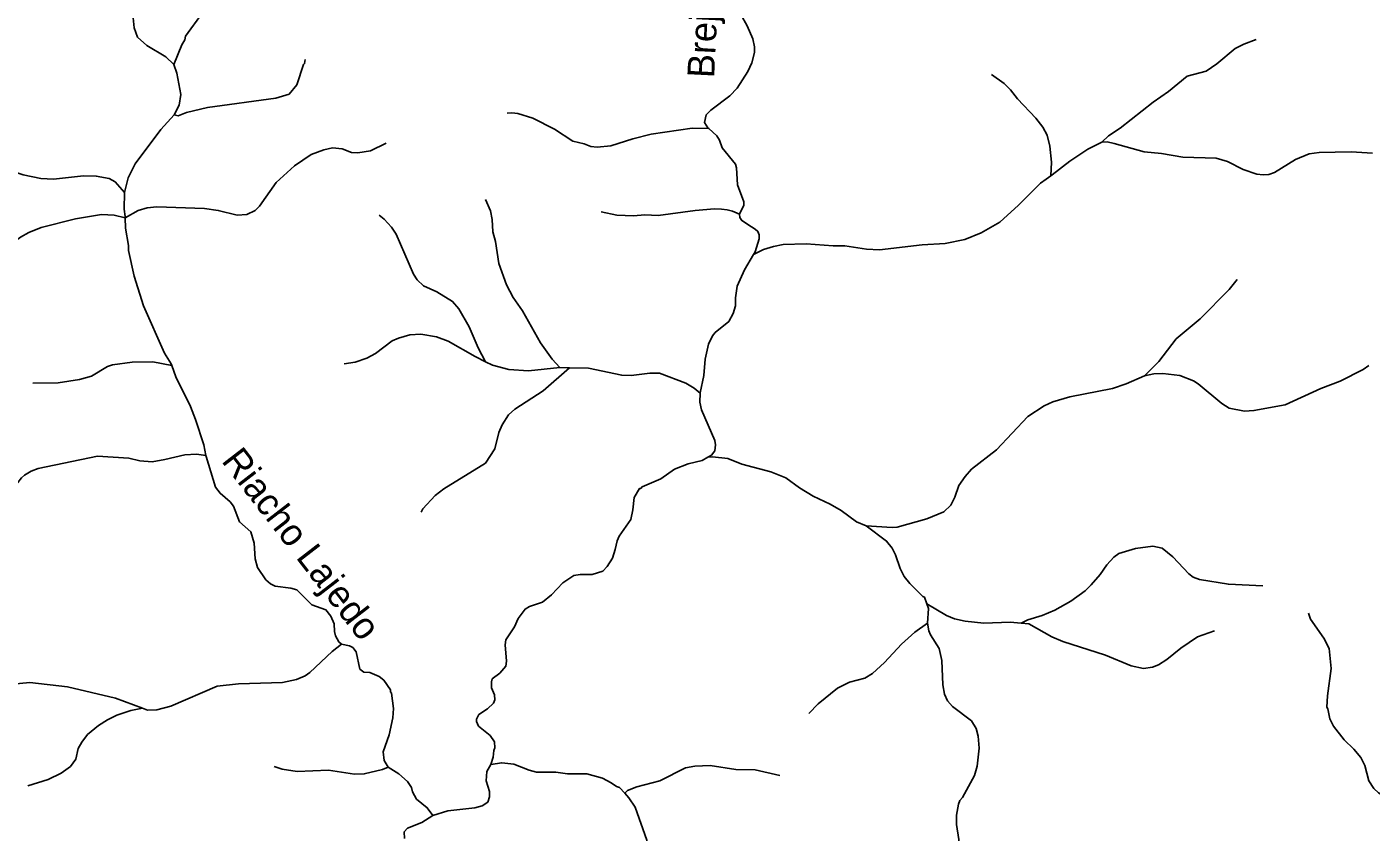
# Model space of a CAD drawing. Extents: x 280.4 to 335.6, y 8893.9 to 8949.5.
# Drawn here: x 294.07 to 304.07, y 8901.81 to 8907.81 of the extents above; entities that cross this region are included whole.
import ezdxf
from ezdxf.enums import TextEntityAlignment as Align

# ---------------------------------------------------------------- set-up
doc = ezdxf.new("R2010")
doc.units = 0
doc.header["$LTSCALE"] = 0.064
doc.layers.add('61', color=7, linetype='Continuous')
doc.layers.add('7', color=7, linetype='Continuous', lineweight=25)

msp = doc.modelspace()

# ---------------------------------------------------------------- linework, layer by layer
at = {"layer": '7'}
msp.add_line((298.0338, 8905.2741), (298.1057, 8905.2723), dxfattribs=at)
for points in [[(294.8695, 8909.4372), (294.8283, 8909.3018), (294.8149, 8909.1389), (294.8292, 8908.9278), (294.8261, 8908.7854), (294.8339, 8908.6824), (294.8294, 8908.6447), (294.8548, 8908.2587), (294.8485, 8907.9772), (294.8641, 8907.8037), (294.8903, 8907.7352), (294.9604, 8907.6727), (295.1005, 8907.5881), (295.1595, 8907.5317)], [(295.7286, 8908.5113), (295.6344, 8908.4215), (295.5944, 8908.3911), (295.545, 8908.3341), (295.5236, 8908.2978), (295.5089, 8908.2555), (295.4944, 8908.1353), (295.4452, 8908.056), (295.4328, 8908.0148), (295.3726, 8907.9159), (295.2472, 8907.742), (295.242, 8907.7151), (295.2196, 8907.6788), (295.1595, 8907.5317)], [(299.5995, 8908.4727), (299.5837, 8908.4131), (299.5528, 8908.3621), (299.4083, 8908.1337), (299.3696, 8907.9971), (299.3708, 8907.936), (299.3805, 8907.905), (299.429, 8907.8189), (299.47, 8907.7227), (299.4831, 8907.6637), (299.483, 8907.6204), (299.4626, 8907.5439), (299.4338, 8907.4796), (299.354, 8907.3549), (299.2995, 8907.2988), (299.1586, 8907.1913), (299.1244, 8907.1555), (299.1108, 8907.1), (299.1368, 8907.0604), (299.1432, 8907.0543)], [(303.2179, 8907.7171), (303.1251, 8907.6829), (303.061, 8907.6512), (302.9262, 8907.5368), (302.8453, 8907.4825), (302.7046, 8907.4438), (302.5663, 8907.3303), (302.4507, 8907.2508), (302.2057, 8907.0574), (302.1194, 8906.9994), (302.069, 8906.9533)], [(296.1383, 8907.5687), (296.1335, 8907.5381), (296.1259, 8907.5321), (296.0763, 8907.3792), (296.0182, 8907.3101), (295.9188, 8907.2795), (295.4107, 8907.2101), (295.2547, 8907.1735), (295.1931, 8907.1499), (295.1615, 8907.1572)], [(295.1595, 8907.5317), (295.1828, 8907.4657), (295.213, 8907.3069), (295.1998, 8907.228), (295.1615, 8907.1572)], [(301.2477, 8907.4576), (301.3414, 8907.3894), (301.3899, 8907.3425), (301.4401, 8907.2755), (301.5781, 8907.1319), (301.6293, 8907.0647), (301.6615, 8907.0048), (301.6817, 8906.922), (301.6933, 8906.804), (301.6899, 8906.7017)], [(295.1615, 8907.1572), (295.064, 8907.0479), (294.8719, 8906.7911), (294.8213, 8906.6857), (294.7927, 8906.5766)], [(297.643, 8907.1676), (297.6764, 8907.1717), (297.7201, 8907.1656), (297.8333, 8907.1317), (297.9946, 8907.0492), (298.1312, 8906.9596), (298.2162, 8906.9396), (298.2638, 8906.9194), (298.3118, 8906.9145), (298.4138, 8906.9245), (298.5786, 8906.9769), (298.7136, 8907.0122), (299.0193, 8907.0567), (299.1432, 8907.0543)], [(293.4645, 8907.075), (293.4843, 8907.0451), (293.503, 8907.022), (293.5465, 8906.9755), (293.7187, 8906.8413), (293.848, 8906.7734), (294.0376, 8906.7086), (294.17, 8906.6822), (294.2639, 8906.6762), (294.487, 8906.7017), (294.5829, 8906.7001), (294.6796, 8906.6821), (294.7243, 8906.656), (294.7927, 8906.5766)], [(299.1432, 8907.0543), (299.2016, 8906.999), (299.222, 8906.9678), (299.2427, 8906.9112), (299.3423, 8906.7888), (299.3487, 8906.7617), (299.3557, 8906.6348), (299.4031, 8906.5091), (299.4027, 8906.4839), (299.3705, 8906.4168)], [(296.741, 8906.9446), (296.6242, 8906.8892), (296.529, 8906.873), (296.4818, 8906.8758), (296.4144, 8906.9019), (296.3422, 8906.9111), (296.2775, 8906.8966), (296.1829, 8906.8604), (296.0576, 8906.7768), (295.9221, 8906.6523), (295.7984, 8906.4747), (295.7658, 8906.4439), (295.7035, 8906.4126), (295.6314, 8906.4092), (295.4913, 8906.4442), (295.3875, 8906.4585), (295.0339, 8906.4714), (294.9619, 8906.4631), (294.894, 8906.4444), (294.7989, 8906.3885)], [(302.069, 8906.9533), (301.9658, 8906.9004), (301.8302, 8906.81), (301.6984, 8906.7094), (301.6899, 8906.7017)], [(304.0851, 8906.8713), (303.9252, 8906.8806), (303.6866, 8906.876), (303.6131, 8906.8649), (303.5101, 8906.8232), (303.3549, 8906.7259), (303.3115, 8906.711), (303.2702, 8906.7082), (303.2227, 8906.7145), (303.1205, 8906.748), (303.0039, 8906.8075), (302.9199, 8906.8325), (302.6728, 8906.8408), (302.5138, 8906.8678), (302.3834, 8906.881), (302.1609, 8906.943), (302.1081, 8906.9542), (302.069, 8906.9533)], [(301.6899, 8906.7017), (301.654, 8906.678), (301.6119, 8906.6459), (301.4497, 8906.4821), (301.3104, 8906.356), (301.1716, 8906.2777), (301.0499, 8906.2276), (300.9025, 8906.1979), (300.7306, 8906.1867), (300.4145, 8906.1516), (300.3181, 8906.1557), (300.1564, 8906.1802), (300.0677, 8906.1805), (299.8669, 8906.1963), (299.6958, 8906.19), (299.6248, 8906.1747), (299.5509, 8906.1533), (299.4759, 8906.1159)], [(294.7927, 8906.5766), (294.7908, 8906.4524), (294.7987, 8906.4), (294.7989, 8906.3885)], [(297.48, 8906.5262), (297.5179, 8906.4413), (297.5306, 8906.3773), (297.5352, 8906.2833), (297.5539, 8906.212), (297.5804, 8906.0476), (297.6373, 8905.89), (297.6872, 8905.796), (297.7552, 8905.6958), (297.8898, 8905.4571), (297.9778, 8905.3349), (298.0338, 8905.2741)], [(298.3421, 8906.433), (298.4571, 8906.4091), (298.5826, 8906.4043), (298.6657, 8906.4121), (298.7662, 8906.4058), (299.0424, 8906.4443), (299.1864, 8906.457), (299.2387, 8906.4526), (299.2791, 8906.4488), (299.3196, 8906.4378), (299.3705, 8906.4168)], [(292.5427, 8905.3746), (292.64, 8905.3696), (292.7205, 8905.3528), (292.8704, 8905.306), (293.0055, 8905.2516), (293.0877, 8905.2352), (293.1335, 8905.2414), (293.1904, 8905.2819), (293.24, 8905.3409), (293.4092, 8905.6973), (293.4775, 8905.7946), (293.5368, 8905.8586), (293.735, 8906.0343), (294.0186, 8906.2449), (294.0802, 8906.2791), (294.1735, 8906.3179), (294.4287, 8906.3817), (294.6213, 8906.4138), (294.7156, 8906.4081), (294.7989, 8906.3885)], [(294.7989, 8906.3885), (294.8003, 8906.3112), (294.8225, 8906.1819), (294.8235, 8906.1455), (294.8649, 8905.9548), (294.9347, 8905.7333), (295.0896, 8905.3814), (295.1407, 8905.3007), (295.1452, 8905.2879)], [(296.6893, 8906.4094), (296.7255, 8906.3795), (296.7813, 8906.3183), (296.8157, 8906.2662), (296.9452, 8905.9692), (296.9707, 8905.9277), (297.0178, 8905.8811), (297.1194, 8905.8365), (297.2357, 8905.7665), (297.2815, 8905.7115), (297.3593, 8905.5758), (297.426, 8905.4204), (297.4803, 8905.3167)], [(299.3705, 8906.4168), (299.3742, 8906.3911), (299.3891, 8906.3684), (299.46, 8906.3228), (299.4893, 8906.3046), (299.5084, 8906.2871), (299.5178, 8906.2613), (299.5183, 8906.2316), (299.4877, 8906.1363), (299.4759, 8906.1159)], [(299.4759, 8906.1159), (299.4099, 8906.0018), (299.3552, 8905.8797), (299.3424, 8905.794), (299.342, 8905.7341), (299.325, 8905.6757), (299.2922, 8905.6169), (299.191, 8905.5347), (299.1713, 8905.5102), (299.1407, 8905.4472), (299.1158, 8905.3355), (299.1056, 8905.2145), (299.0795, 8905.0849), (299.0793, 8905.0817)], [(303.0767, 8905.93), (303.0163, 8905.8547), (302.802, 8905.6374), (302.6237, 8905.4874), (302.4924, 8905.3178), (302.3876, 8905.2117)], [(296.4294, 8905.3003), (296.5107, 8905.314), (296.5974, 8905.3421), (296.662, 8905.3776), (296.7868, 8905.4733), (296.8317, 8905.4925), (296.9173, 8905.5164), (296.9995, 8905.5213), (297.1155, 8905.5023), (297.2018, 8905.4689), (297.4048, 8905.3547), (297.4803, 8905.3167)], [(294.1111, 8905.1567), (294.2983, 8905.1585), (294.4576, 8905.1839), (294.5477, 8905.21), (294.6656, 8905.2819), (294.7046, 8905.2927), (294.8491, 8905.3135), (295.0027, 8905.3166), (295.1452, 8905.2879)], [(295.1452, 8905.2879), (295.1751, 8905.2035), (295.2834, 8904.9841), (295.3224, 8904.8865), (295.384, 8904.6969), (295.3989, 8904.6189)], [(297.0005, 8904.1954), (297.0152, 8904.221), (297.1064, 8904.3201), (297.1695, 8904.3704), (297.4803, 8904.5615), (297.5509, 8904.6668), (297.5804, 8904.7896), (297.6052, 8904.8459), (297.652, 8904.9201), (297.6989, 8904.9621), (297.9094, 8905.0993), (298.1057, 8905.2723)], [(297.4803, 8905.3167), (297.5332, 8905.29), (297.654, 8905.2597), (297.8015, 8905.248), (298.0338, 8905.2741)], [(298.1057, 8905.2723), (298.2478, 8905.2687), (298.4947, 8905.2161), (298.5651, 8905.2145), (298.7041, 8905.2303), (298.7755, 8905.2304), (298.972, 8905.158), (299.0353, 8905.12), (299.0793, 8905.0817)], [(304.0565, 8905.288), (304.0138, 8905.2584), (303.8433, 8905.1715), (303.6994, 8905.117), (303.4352, 8904.9957), (303.2008, 8904.9522), (303.1319, 8904.949), (303.0168, 8904.9701), (302.9622, 8905.0045), (302.787, 8905.1525), (302.7511, 8905.1756), (302.6489, 8905.2146), (302.5234, 8905.2288), (302.4569, 8905.227), (302.3876, 8905.2117)], [(302.3876, 8905.2117), (302.2512, 8905.1522), (302.149, 8905.1164), (301.8316, 8905.0546), (301.7045, 8905.0182), (301.6396, 8904.9893), (301.5179, 8904.9078), (301.2844, 8904.66), (301.0995, 8904.515), (301.0508, 8904.4613), (301.005, 8904.3939), (300.9739, 8904.3067), (300.9451, 8904.2491), (300.8926, 8904.1978), (300.7673, 8904.1472), (300.545, 8904.0838), (300.5084, 8904.0807), (300.3135, 8904.0941)], [(299.0793, 8905.0817), (299.0762, 8905.0161), (299.088, 8904.9593), (299.1869, 8904.7289), (299.1921, 8904.6966), (299.1873, 8904.6522), (299.1622, 8904.6209), (299.1354, 8904.6056)], [(293.7359, 8903.4204), (293.8149, 8903.5442), (293.8423, 8903.6017), (293.8763, 8903.699), (293.9003, 8903.8158), (293.9037, 8903.9683), (293.9137, 8904.0196), (293.9146, 8904.0245), (293.951, 8904.1397), (293.9435, 8904.2555), (293.9724, 8904.381), (294.0251, 8904.4518), (294.0477, 8904.4726), (294.0985, 8904.5011), (294.1512, 8904.5203), (294.5919, 8904.6129), (294.8253, 8904.5971), (294.9071, 8904.5784), (294.9988, 8904.5716), (295.0924, 8904.5871), (295.2425, 8904.6227), (295.3282, 8904.629), (295.3989, 8904.6189)], [(295.3989, 8904.6189), (295.4006, 8904.6098), (295.4694, 8904.3824), (295.5048, 8904.3373), (295.5797, 8904.272), (295.6039, 8904.2403), (295.6501, 8904.1234), (295.7345, 8904.0494), (295.7582, 8903.9644), (295.7661, 8903.8482), (295.7831, 8903.7836), (295.8444, 8903.6926), (295.8806, 8903.6612), (295.9137, 8903.6456), (296.0324, 8903.63), (296.0755, 8903.6171), (296.1883, 8903.5054), (296.2924, 8903.4678), (296.3289, 8903.4205), (296.353, 8903.3631), (296.3567, 8903.3057), (296.365, 8903.2754), (296.3896, 8903.2289), (296.4087, 8903.2135)], [(299.1354, 8904.6056), (299.0932, 8904.5815), (298.9905, 8904.5555), (298.8866, 8904.5162), (298.7851, 8904.4432), (298.6459, 8904.3846), (298.6359, 8904.3723), (298.6272, 8904.3723), (298.5886, 8904.3051), (298.5777, 8904.2125)], [(300.3135, 8904.0941), (300.2436, 8904.1246), (300.1296, 8904.2086), (300.0474, 8904.2553), (299.9202, 8904.3149), (299.8189, 8904.3771), (299.7168, 8904.4513), (299.6054, 8904.4968), (299.3879, 8904.5524), (299.2851, 8904.5965), (299.1714, 8904.6086), (299.1354, 8904.6056)], [(298.5777, 8904.2125), (298.5614, 8904.1423), (298.4748, 8904.0164), (298.4596, 8903.9829), (298.4466, 8903.9183), (298.4252, 8903.8535), (298.386, 8903.7911), (298.3542, 8903.7563), (298.2755, 8903.7303), (298.1845, 8903.7302), (298.1392, 8903.7234), (298.056, 8903.669), (297.9729, 8903.5794), (297.906, 8903.5245), (297.8072, 8903.4935), (297.7758, 8903.4732), (297.7244, 8903.4047), (297.697, 8903.3407), (297.6315, 8903.2441), (297.6265, 8903.2075), (297.6376, 8903.0858), (297.6309, 8903.0476), (297.5873, 8902.9972), (297.5308, 8902.9537), (297.5242, 8902.9306), (297.5257, 8902.8874), (297.5472, 8902.8344), (297.551, 8902.7981), (297.5412, 8902.7719), (297.4943, 8902.7312), (297.4304, 8902.6879), (297.4123, 8902.6525), (297.4131, 8902.6363), (297.4282, 8902.6014), (297.5159, 8902.5307), (297.5466, 8902.4859), (297.5496, 8902.4409), (297.5419, 8902.419), (297.5383, 8902.3709), (297.5193, 8902.3151)], [(300.7674, 8903.5127), (300.7487, 8903.563), (300.7366, 8903.5678), (300.6394, 8903.6646), (300.5963, 8903.7176), (300.5675, 8903.7751), (300.5335, 8903.8781), (300.5082, 8903.9286), (300.4661, 8903.9801), (300.3135, 8904.0941)], [(303.268, 8903.647), (303.0111, 8903.6584), (302.7959, 8903.6944), (302.7487, 8903.7122), (302.7158, 8903.7361), (302.5989, 8903.8641), (302.5191, 8903.9267), (302.4499, 8903.9413), (302.3195, 8903.9258), (302.1955, 8903.8869), (302.1576, 8903.8618), (302.1064, 8903.8044), (302.0567, 8903.7308), (301.9909, 8903.6538), (301.9443, 8903.6104), (301.8394, 8903.5323), (301.7194, 8903.4651), (301.6251, 8903.4267), (301.5189, 8903.3944), (301.4682, 8903.3691)], [(301.4682, 8903.3691), (301.387, 8903.3767), (301.1897, 8903.369), (301.0523, 8903.3828), (300.972, 8903.402), (300.9138, 8903.4261), (300.7674, 8903.5127)], [(300.7723, 8903.3679), (300.7799, 8903.479), (300.7674, 8903.5127)], [(303.6087, 8903.4422), (303.6222, 8903.3994), (303.7231, 8903.2571), (303.7628, 8903.1795), (303.7755, 8903.0307), (303.7483, 8902.8276), (303.7438, 8902.7427), (303.7513, 8902.7306), (303.7676, 8902.6557), (303.795, 8902.6006), (303.8739, 8902.4998), (303.945, 8902.4301), (303.9981, 8902.3671), (304.0268, 8902.3094), (304.0571, 8902.1951), (304.0946, 8902.138), (304.1285, 8902.1059), (304.2777, 8902.011), (304.3336, 8901.9647), (304.3851, 8901.9001), (304.4165, 8901.8377)], [(299.8869, 8902.695), (299.9581, 8902.7675), (300.1017, 8902.885), (300.1894, 8902.9288), (300.3057, 8902.9582), (300.3622, 8902.9927), (300.4522, 8903.0762), (300.5771, 8903.2121), (300.6778, 8903.3016), (300.7723, 8903.3679)], [(301.0142, 8901.5392), (301.0074, 8901.5778), (301.001, 8901.5839), (301.004, 8901.7568), (300.9881, 8901.868), (300.9866, 8901.9374), (301.0012, 8902.02), (301.0114, 8902.0464), (301.0309, 8902.0705), (301.1211, 8902.2348), (301.14, 8902.3044), (301.1558, 8902.4383), (301.148, 8902.5262), (301.1336, 8902.583), (301.0977, 8902.6399), (300.9577, 8902.7468), (300.9206, 8902.7911), (300.8972, 8902.8389), (300.8858, 8902.91), (300.8791, 8903.0905), (300.8583, 8903.1801), (300.7928, 8903.281), (300.7802, 8903.3113), (300.7723, 8903.3679)], [(302.9071, 8903.3129), (302.7803, 8903.2659), (302.6582, 8903.1835), (302.5521, 8903.097), (302.4913, 8903.0587), (302.4471, 8903.0399), (302.3799, 8903.0318), (302.2865, 8903.0497), (302.0956, 8903.1308), (301.7795, 8903.2326), (301.6957, 8903.2678), (301.5251, 8903.3638), (301.4682, 8903.3691)], [(294.9279, 8902.7347), (294.9631, 8902.7214), (295.0341, 8902.7224), (295.1377, 8902.7501), (295.4817, 8902.8986), (295.6417, 8902.9178), (295.9687, 8902.9275), (296.0735, 8902.9483), (296.1379, 8902.9772), (296.1732, 8903.0015), (296.3391, 8903.1565), (296.4087, 8903.2135)], [(296.4087, 8903.2135), (296.468, 8903.2), (296.4919, 8903.1869), (296.5166, 8903.1554), (296.5451, 8903.0273), (296.5737, 8903.0047), (296.6198, 8903.0012), (296.6901, 8902.9725), (296.724, 8902.9438), (296.7734, 8902.8712), (296.7726, 8902.8563), (296.7802, 8902.8484), (296.7962, 8902.7323), (296.7896, 8902.6635), (296.7643, 8902.5372), (296.7198, 8902.4093), (296.7264, 8902.3448), (296.7552, 8902.2952)], [(292.7905, 8902.4034), (292.8465, 8902.3843), (292.9206, 8902.3715), (292.9965, 8902.3694), (293.2518, 8902.4331), (293.2809, 8902.435), (293.3498, 8902.4688), (293.4022, 8902.5065), (293.4971, 8902.5932), (293.5794, 8902.6533), (293.6704, 8902.733), (293.7187, 8902.786), (293.7946, 8902.8459), (293.8819, 8902.8967), (293.9336, 8902.913), (294.0872, 8902.9274), (294.3693, 8902.8936), (294.7269, 8902.8107), (294.9279, 8902.7347)], [(294.0736, 8902.1565), (294.2253, 8902.2034), (294.3213, 8902.2513), (294.3907, 8902.3007), (294.4304, 8902.3551), (294.449, 8902.4356), (294.4749, 8902.4831), (294.5165, 8902.5393), (294.5995, 8902.6064), (294.6659, 8902.6483), (294.7351, 8902.6822), (294.8396, 8902.718), (294.9279, 8902.7347)], [(295.9065, 8902.3019), (295.9657, 8902.282), (296.0791, 8902.2631), (296.3116, 8902.2732), (296.5044, 8902.243), (296.5782, 8902.246), (296.7126, 8902.2781), (296.7552, 8902.2952)], [(296.7552, 8902.2952), (296.8351, 8902.2472), (296.9003, 8902.1902), (296.9301, 8902.144), (296.9375, 8902.1121), (296.9675, 8902.058), (297.0474, 8901.9935), (297.0881, 8901.9353)], [(297.5193, 8902.3151), (297.4893, 8902.2639), (297.4854, 8902.1949), (297.5096, 8902.1134), (297.5096, 8902.0747), (297.4967, 8902.0359), (297.4553, 8902.0089), (297.4008, 8901.992), (297.2001, 8901.9712), (297.0881, 8901.9353)], [(298.5182, 8902.1017), (298.4792, 8902.1454), (298.4547, 8902.1522), (298.4165, 8902.1799), (298.3515, 8902.2139), (298.2357, 8902.2461), (298.091, 8902.2462), (298.0054, 8902.2589), (297.8614, 8902.259), (297.8046, 8902.2747), (297.6903, 8902.3192), (297.6016, 8902.3292), (297.5193, 8902.3151)], [(299.6715, 8902.2348), (299.4882, 8902.2751), (299.3455, 8902.2782), (299.1536, 8902.3085), (299.0392, 8902.3038), (298.9694, 8902.2912), (298.7787, 8902.1948), (298.6067, 8902.1502), (298.5385, 8902.1216), (298.5182, 8902.1017)], [(298.7974, 8901.2278), (298.7987, 8901.3417), (298.7925, 8901.3543), (298.7792, 8901.4599), (298.7262, 8901.6422), (298.6884, 8901.7153), (298.6815, 8901.7511), (298.5951, 8901.9974), (298.5486, 8902.0677), (298.5182, 8902.1017)], [(297.0881, 8901.9353), (297.0074, 8901.8832), (296.8999, 8901.8419), (296.8753, 8901.813), (296.8783, 8901.7652)]]:
    msp.add_lwpolyline(points, dxfattribs=at)

# ---------------------------------------------------------------- texts
at = {"layer": '61'}
for s, rotation, p in [('Brejo Mutum', 87.149, (299.2202, 8908.1845)), ('Riacho Lajedo', 307.694, (296.0318, 8903.9001))]:
    msp.add_text(s, height=0.2, rotation=rotation, dxfattribs=at).set_placement(p, align=Align.CENTER)

doc.saveas('drawing.dxf')
